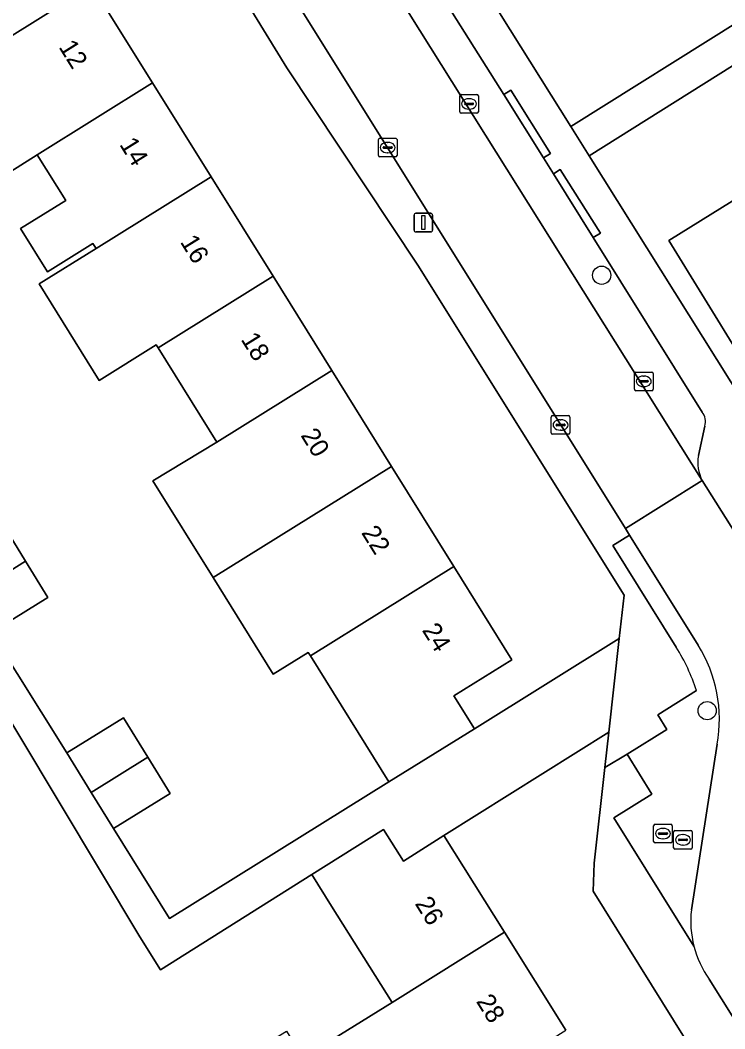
# Model space of a CAD drawing. Extents: x 159352 to 160617, y 385888 to 387323.
# Drawn here: x 159633.7 to 159671.4, y 386029 to 386083.1 of the extents above; entities that cross this region are included whole.
import ezdxf

# ---------------------------------------------------------------- set-up
doc = ezdxf.new("R2010")
doc.units = 0
for name, color, linetype in [('IMGEO_Boom', 7, 'Continuous'), ('IMGEO_Erf', 7, 'Continuous'), ('IMGEO_Kolk', 7, 'Continuous'), ('IMGEO_Lichtmast', 7, 'Continuous'), ('IMGEO_Pand', 7, 'Continuous'), ('IMGEO_Pand_nummerreeks', 7, 'Continuous'), ('IMGEO_Parkeervlak_open', 7, 'Continuous'), ('IMGEO_Rijbaan_lokaal_open', 7, 'Continuous'), ('IMGEO_Rioolput', 7, 'Continuous'), ('IMGEO_Voetpad_gesloten', 7, 'Continuous'), ('IMGEO_Voetpad_open', 7, 'Continuous')]:
    doc.layers.add(name, color=color, linetype=linetype)

msp = doc.modelspace()

# ---------------------------------------------------------------- linework, layer by layer
at = {"layer": 'IMGEO_Boom'}
for centre in [(159664.845, 386069.396), (159670.504, 386046.035)]:
    msp.add_circle(centre, 0.489, dxfattribs=at)
at = {"layer": 'IMGEO_Erf'}
for points in [[(159627.21, 386134.74), (159663.189, 386077.37), (159672.327, 386083.101)], [(159633.335, 386090.188), (159633.988, 386090.595), (159637.508, 386084.943), (159640.76, 386079.72), (159643.901, 386074.676), (159647.225, 386069.338), (159650.372, 386064.285), (159653.576, 386059.14), (159656.924, 386053.763), (159660.035, 386048.768), (159656.92, 386046.828), (159658.02, 386045.063), (159665.788, 386049.899), (159666.048, 386052.236), (159654.99, 386069.935), (159647.967, 386080.518), (159644.145, 386086.744), (159642.808, 386089.045), (159635.064, 386101.827), (159618.898, 386127.7)], [(159682.021, 386086.971), (159675.765, 386083.062), (159677.645, 386080.051), (159675.693, 386078.833), (159673.743, 386077.616), (159671.864, 386080.628), (159664.171, 386075.803), (159675.622, 386057.544), (159678.147, 386053.368), (159680.364, 386052.973), (159727.06, 386082.254), (159727.834, 386084.857)], [(159715.741, 386083.528), (159710.62, 386080.324), (159705.257, 386076.97), (159700.341, 386073.894), (159694.987, 386070.545), (159689.802, 386067.302), (159684.835, 386064.194), (159679.316, 386060.742), (159677.344, 386063.895), (159674.183, 386061.917), (159668.443, 386071.26), (159671.836, 386073.379), (159671.913, 386073.256), (159673.873, 386070.118), (159679.098, 386073.381), (159679.277, 386073.094), (159684.247, 386076.198), (159689.434, 386079.437), (159694.775, 386082.772), (159696.55, 386079.963), (159701.469, 386083.035), (159701.464, 386083.043), (159699.747, 386085.796)], [(159632.649, 386056.162), (159633.952, 386054.046), (159635.149, 386052.102), (159632.11, 386050.23), (159636.161, 386043.768), (159639.201, 386045.64), (159640.501, 386043.529), (159641.701, 386041.58), (159638.662, 386039.708), (159641.668, 386034.881), (159653.436, 386042.209), (159649.228, 386048.967), (159649.107, 386049.161), (159647.231, 386047.993), (159644.004, 386053.176), (159640.778, 386058.358), (159644.204, 386060.439), (159641.057, 386065.493), (159640.957, 386065.654), (159637.903, 386063.751), (159634.677, 386068.927), (159637.732, 386070.832), (159637.564, 386071.102), (159635.122, 386069.581), (159633.679, 386071.898), (159636.102, 386073.407), (159634.575, 386075.859), (159630.164, 386073.091)], [(159657.055, 386018.155), (159655.352, 386020.863), (159653.88, 386023.203), (159652.165, 386025.931), (159652.161, 386025.928), (159649.796, 386025.831), (159647.968, 386024.7), (159646.105, 386023.548), (159644.243, 386026.558), (159646.106, 386027.71), (159647.934, 386028.841), (159648.826, 386027.399), (159653.609, 386030.374), (159650.359, 386035.544), (159649.294, 386037.237), (159641.179, 386032.132), (159640.082, 386033.894), (159625.017, 386059.01)], [(159676.127, 386017.48), (159664.396, 386036.344), (159664.447, 386037.85), (159665.019, 386042.984), (159665.23, 386044.882), (159656.379, 386039.338), (159659.625, 386034.156), (159662.923, 386028.89)]]:
    msp.add_lwpolyline(points, dxfattribs=at)
at = {"layer": 'IMGEO_Kolk'}
for p, q in [((159657.231, 386078.164), (159657.231, 386079.016)), ((159657.306, 386079.09), (159658.158, 386079.09)), ((159657.49, 386078.584), (159657.49, 386078.596)), ((159657.533, 386078.633), (159657.931, 386078.633)), ((159657.719, 386078.87), (159657.744, 386078.87)), ((159657.974, 386078.596), (159657.974, 386078.584)), ((159658.232, 386079.016), (159658.232, 386078.164)), ((159658.158, 386078.09), (159657.306, 386078.09)), ((159657.928, 386078.547), (159657.53, 386078.547)), ((159657.742, 386078.31), (159657.717, 386078.31)), ((159652.871, 386075.819), (159652.871, 386076.671)), ((159652.946, 386076.745), (159653.798, 386076.745)), ((159653.359, 386076.525), (159653.384, 386076.525)), ((159653.872, 386076.671), (159653.872, 386075.819)), ((159653.13, 386076.239), (159653.13, 386076.251)), ((159653.568, 386076.202), (159653.17, 386076.202)), ((159653.173, 386076.288), (159653.571, 386076.288)), ((159653.382, 386075.965), (159653.357, 386075.965)), ((159653.614, 386076.251), (159653.614, 386076.239)), ((159653.798, 386075.745), (159652.946, 386075.745)), ((159666.602, 386063.276), (159666.602, 386064.128)), ((159666.677, 386064.202), (159667.529, 386064.202)), ((159667.09, 386063.982), (159667.115, 386063.982)), ((159667.603, 386064.128), (159667.603, 386063.276)), ((159666.861, 386063.696), (159666.861, 386063.708)), ((159667.299, 386063.659), (159666.901, 386063.659)), ((159666.904, 386063.745), (159667.302, 386063.745)), ((159667.113, 386063.422), (159667.088, 386063.422)), ((159667.345, 386063.708), (159667.345, 386063.696)), ((159667.529, 386063.202), (159666.677, 386063.202)), ((159662.138, 386060.936), (159662.138, 386061.788)), ((159662.213, 386061.862), (159663.065, 386061.862)), ((159663.139, 386061.788), (159663.139, 386060.936)), ((159662.397, 386061.356), (159662.397, 386061.368)), ((159662.835, 386061.319), (159662.437, 386061.319)), ((159662.44, 386061.405), (159662.838, 386061.405)), ((159662.626, 386061.642), (159662.651, 386061.642)), ((159662.881, 386061.368), (159662.881, 386061.356)), ((159663.065, 386060.862), (159662.213, 386060.862)), ((159662.649, 386061.082), (159662.624, 386061.082))]:
    msp.add_line(p, q, dxfattribs=at)
for points in [[(159657.231, 386078.164), (159657.231, 386079.016)], [(159657.306, 386079.09), (159658.158, 386079.09)], [(159658.232, 386079.016), (159658.232, 386078.164)], [(159658.158, 386078.09), (159657.306, 386078.09)], [(159652.871, 386075.819), (159652.871, 386076.671)], [(159652.946, 386076.745), (159653.798, 386076.745)], [(159653.872, 386076.671), (159653.872, 386075.819)], [(159653.798, 386075.745), (159652.946, 386075.745)], [(159666.602, 386063.276), (159666.602, 386064.128)], [(159666.677, 386064.202), (159667.529, 386064.202)], [(159667.603, 386064.128), (159667.603, 386063.276)], [(159667.529, 386063.202), (159666.677, 386063.202)], [(159662.138, 386060.936), (159662.138, 386061.788)], [(159662.213, 386061.862), (159663.065, 386061.862)], [(159663.139, 386061.788), (159663.139, 386060.936)], [(159663.065, 386060.862), (159662.213, 386060.862)]]:
    msp.add_lwpolyline(points, dxfattribs=at)
for centre, radius, start, end in [((159657.308, 386079.014), 0.0765, 91.552, 178.448), ((159657.308, 386079.014), 0.0765, 91.552, 178.448), ((159657.53, 386078.593), 0.0403, 85.8775, 175.7526), ((159657.527, 386078.583), 0.0366, 178.938, 274.7102), ((159657.931, 386078.59), 0.043, 264.8664, 352.4533), ((159657.935, 386078.595), 0.0386, 1.7309, 96.639), ((159658.156, 386079.014), 0.0765, 1.552, 88.448), ((159658.156, 386079.014), 0.0765, 1.552, 88.448), ((159657.308, 386078.166), 0.0765, 181.552, 268.448), ((159657.308, 386078.166), 0.0765, 181.552, 268.448), ((159658.156, 386078.166), 0.0765, 271.552, 358.448), ((159658.156, 386078.166), 0.0765, 271.552, 358.448), ((159652.948, 386076.669), 0.0765, 91.552, 178.448), ((159652.948, 386076.669), 0.0765, 91.552, 178.448), ((159653.796, 386076.669), 0.0765, 1.552, 88.448), ((159653.796, 386076.669), 0.0765, 1.552, 88.448), ((159653.17, 386076.248), 0.0403, 85.8775, 175.7526), ((159653.167, 386076.238), 0.0366, 178.938, 274.7102), ((159653.571, 386076.245), 0.043, 264.8664, 352.4533), ((159653.575, 386076.25), 0.0386, 1.7309, 96.639), ((159652.948, 386075.821), 0.0765, 181.552, 268.448), ((159652.948, 386075.821), 0.0765, 181.552, 268.448), ((159653.796, 386075.821), 0.0765, 271.552, 358.448), ((159653.796, 386075.821), 0.0765, 271.552, 358.448), ((159666.679, 386064.126), 0.0765, 91.552, 178.448), ((159666.679, 386064.126), 0.0765, 91.552, 178.448), ((159667.527, 386064.126), 0.0765, 1.552, 88.448), ((159667.527, 386064.126), 0.0765, 1.552, 88.448), ((159666.901, 386063.705), 0.0403, 85.8775, 175.7526), ((159666.898, 386063.695), 0.0366, 178.938, 274.7102), ((159667.302, 386063.702), 0.043, 264.8664, 352.4533), ((159667.306, 386063.707), 0.0386, 1.7309, 96.639), ((159666.679, 386063.278), 0.0765, 181.552, 268.448), ((159666.679, 386063.278), 0.0765, 181.552, 268.448), ((159667.527, 386063.278), 0.0765, 271.552, 358.448), ((159667.527, 386063.278), 0.0765, 271.552, 358.448), ((159662.215, 386061.786), 0.0765, 91.552, 178.448), ((159662.215, 386061.786), 0.0765, 91.552, 178.448), ((159663.063, 386061.786), 0.0765, 1.552, 88.448), ((159663.063, 386061.786), 0.0765, 1.552, 88.448), ((159662.437, 386061.365), 0.0403, 85.8775, 175.7526), ((159662.434, 386061.355), 0.0366, 178.938, 274.7102), ((159662.838, 386061.362), 0.043, 264.8664, 352.4533), ((159662.842, 386061.367), 0.0386, 1.7309, 96.639), ((159662.215, 386060.938), 0.0765, 181.552, 268.448), ((159662.215, 386060.938), 0.0765, 181.552, 268.448), ((159663.063, 386060.938), 0.0765, 271.552, 358.448), ((159663.063, 386060.938), 0.0765, 271.552, 358.448)]:
    msp.add_arc(centre, radius, start, end, dxfattribs=at)
for centre, major_axis, ratio, start_param, end_param in [((159657.718, 386078.59), (-0.387, 0.002), 0.722429, 4.712389, 7.853982), ((159657.743, 386078.59), (-0.39, 0.002), 0.717154, 1.570796, 4.712389), ((159653.358, 386076.245), (-0.387, 0.002), 0.722429, 4.712389, 7.853982), ((159653.383, 386076.245), (-0.39, 0.002), 0.717154, 1.570796, 4.712389), ((159667.089, 386063.702), (-0.387, 0.002), 0.722429, 4.712389, 7.853982), ((159667.114, 386063.702), (-0.39, 0.002), 0.717154, 1.570796, 4.712389), ((159662.625, 386061.362), (-0.387, 0.002), 0.722429, 4.712389, 7.853982), ((159662.65, 386061.362), (-0.39, 0.002), 0.717154, 1.570796, 4.712389)]:
    msp.add_ellipse(centre, major_axis=major_axis, ratio=ratio, start_param=start_param, end_param=end_param, dxfattribs=at)
at = {"layer": 'IMGEO_Lichtmast'}
for p, q in [((159654.784, 386071.818), (159654.784, 386072.618)), ((159654.784, 386072.618), (159654.784, 386071.818)), ((159654.884, 386072.718), (159655.674, 386072.718)), ((159655.674, 386072.718), (159654.884, 386072.718)), ((159655.774, 386072.618), (159655.774, 386071.818)), ((159655.774, 386071.818), (159655.774, 386072.618)), ((159655.674, 386071.718), (159654.884, 386071.718)), ((159654.884, 386071.718), (159655.674, 386071.718))]:
    msp.add_line(p, q, dxfattribs=at)
msp.add_lwpolyline([(159655.204, 386072.593), (159655.354, 386072.593), (159655.354, 386071.843), (159655.204, 386071.843), (159655.204, 386072.593)], dxfattribs=at)
for centre, start, end in [((159654.884, 386072.618), 90, 180), ((159654.884, 386072.618), 90, 180), ((159655.674, 386072.618), 0, 90), ((159655.674, 386072.618), 360, 90), ((159654.884, 386071.818), 180, 270), ((159654.884, 386071.818), 180, 270), ((159655.674, 386071.818), 270, 0), ((159655.674, 386071.818), 270, 0)]:
    msp.add_arc(centre, 0.1, start, end, dxfattribs=at)
at = {"layer": 'IMGEO_Pand'}
for points in [[(159628.789, 386079.509), (159637.508, 386084.943), (159633.988, 386090.595), (159633.335, 386090.188), (159631.369, 386093.346), (159627.125, 386090.704), (159623.305, 386088.325), (159625.42, 386084.93), (159627.206, 386082.05)], [(159640.76, 386079.72), (159637.508, 386084.943), (159628.789, 386079.509), (159626.901, 386078.332), (159624.337, 386076.711), (159627.574, 386071.502), (159630.164, 386073.091), (159634.575, 386075.859)], [(159634.575, 386075.859), (159636.102, 386073.407), (159633.679, 386071.898), (159635.122, 386069.581), (159637.564, 386071.102), (159637.732, 386070.832), (159643.901, 386074.676), (159640.76, 386079.72)], [(159643.901, 386074.676), (159637.732, 386070.832), (159634.677, 386068.927), (159637.903, 386063.751), (159640.957, 386065.654), (159641.057, 386065.493), (159647.225, 386069.338)], [(159679.098, 386073.381), (159673.873, 386070.118), (159671.913, 386073.256), (159671.836, 386073.379), (159668.443, 386071.26), (159674.183, 386061.917), (159677.344, 386063.895), (159679.316, 386060.742), (159684.835, 386064.194), (159679.277, 386073.094)], [(159641.057, 386065.493), (159644.204, 386060.439), (159650.372, 386064.285), (159647.225, 386069.338)], [(159644.204, 386060.439), (159640.778, 386058.358), (159644.004, 386053.176), (159653.576, 386059.14), (159650.372, 386064.285)], [(159644.004, 386053.176), (159647.231, 386047.993), (159649.107, 386049.161), (159649.228, 386048.967), (159656.924, 386053.763), (159653.576, 386059.14)], [(159632.649, 386056.162), (159629.609, 386054.29), (159630.923, 386052.158), (159633.952, 386054.046)], [(159632.11, 386050.23), (159635.149, 386052.102), (159633.952, 386054.046), (159630.923, 386052.158)], [(159649.228, 386048.967), (159653.436, 386042.209), (159658.02, 386045.063), (159656.92, 386046.828), (159660.035, 386048.768), (159656.924, 386053.763)], [(159639.201, 386045.64), (159636.161, 386043.768), (159637.472, 386041.641), (159640.501, 386043.529)], [(159638.662, 386039.708), (159641.701, 386041.58), (159640.501, 386043.529), (159637.472, 386041.641)], [(159653.609, 386030.374), (159659.625, 386034.156), (159656.379, 386039.338), (159654.21, 386037.964), (159653.146, 386039.658), (159649.294, 386037.237), (159650.359, 386035.544)], [(159662.923, 386028.89), (159659.625, 386034.156), (159653.609, 386030.374), (159648.826, 386027.399), (159649.796, 386025.831), (159652.161, 386025.928), (159652.165, 386025.931), (159653.88, 386023.203), (159656.916, 386025.112)]]:
    msp.add_lwpolyline(points, close=True, dxfattribs=at)
at = {"layer": 'IMGEO_Parkeervlak_open'}
for points in [[(159626.512, 386128.107), (159670.239, 386058.378)], [(159670.242, 386062.057), (159664.392, 386071.428), (159662.26, 386074.831), (159661.719, 386075.692), (159659.596, 386079.097), (159656.115, 386084.635), (159653.983, 386088.042), (159647.039, 386099.116), (159644.917, 386102.518), (159632.416, 386122.422), (159629.965, 386126.37)], [(159670.034, 386059.718), (159670.381, 386061.303)], [(159670.019, 386049.55), (159666.336, 386055.453), (159665.438, 386054.888), (159668.845, 386049.431)], [(159669.924, 386047.11), (159667.856, 386045.816), (159668.331, 386045.027), (159666.211, 386043.692), (159667.526, 386041.555), (159665.503, 386040.276), (159669.792, 386033.391)], [(159669.657, 386035.343), (159671.038, 386044.235)]]:
    msp.add_lwpolyline(points, dxfattribs=at)
for centre, radius, start, end in [((159669.491, 386061.529), 0.918, 345.7688, 35.1217), ((159672.021, 386059.336), 2.024, 169.1278, 208.2681), ((159660.275, 386044.036), 10.126, 17.6727, 32.1934), ((159663.605, 386045.565), 7.551, 349.8541, 31.8521), ((159674.943, 386034.728), 5.322, 173.3631, 194.5494)]:
    msp.add_arc(centre, radius, start, end, dxfattribs=at)
at = {"layer": 'IMGEO_Rijbaan_lokaal_open'}
msp.add_lwpolyline([(159641.564, 386095.152), (159645.806, 386088.37), (159647.92, 386084.96), (159666.118, 386055.802), (159670.239, 386058.378), (159626.512, 386128.107), (159625.752, 386129.326), (159621.761, 386126.823), (159624.572, 386122.299), (159628.257, 386116.428), (159635.697, 386104.535), (159638.89, 386099.412), (159639.428, 386098.549)], close=True, dxfattribs=at)
for points in [[(159674.287, 386051.938), (159670.239, 386058.378), (159666.118, 386055.802), (159666.336, 386055.453), (159670.019, 386049.55)], [(159671.038, 386044.235), (159669.657, 386035.343)], [(159670.612, 386031.633), (159672.6, 386028.467), (159676.243, 386030.847), (159675.949, 386031.202), (159674.928, 386032.924)]]:
    msp.add_lwpolyline(points, dxfattribs=at)
for centre, radius, start, end in [((159663.605, 386045.565), 7.551, 349.8541, 31.8521), ((159674.943, 386034.728), 5.322, 173.3631, 194.5494), ((159674.998, 386034.749), 5.381, 194.6212, 215.3912)]:
    msp.add_arc(centre, radius, start, end, dxfattribs=at)
at = {"layer": 'IMGEO_Rioolput'}
for p, q in [((159667.632, 386039.01), (159667.632, 386039.862)), ((159667.707, 386039.936), (159668.559, 386039.936)), ((159668.12, 386039.716), (159668.145, 386039.716)), ((159668.633, 386039.862), (159668.633, 386039.01)), ((159668.777, 386039.602), (159669.629, 386039.602)), ((159667.891, 386039.43), (159667.891, 386039.442)), ((159668.329, 386039.393), (159667.931, 386039.393)), ((159667.934, 386039.479), (159668.332, 386039.479)), ((159668.143, 386039.156), (159668.118, 386039.156)), ((159668.375, 386039.442), (159668.375, 386039.43)), ((159668.702, 386038.676), (159668.702, 386039.528)), ((159668.961, 386039.096), (159668.961, 386039.108)), ((159669.399, 386039.059), (159669.001, 386039.059)), ((159669.004, 386039.145), (159669.402, 386039.145)), ((159669.19, 386039.382), (159669.215, 386039.382)), ((159669.445, 386039.108), (159669.445, 386039.096)), ((159669.703, 386039.528), (159669.703, 386038.676)), ((159668.559, 386038.936), (159667.707, 386038.936)), ((159669.629, 386038.602), (159668.777, 386038.602)), ((159669.213, 386038.822), (159669.188, 386038.822))]:
    msp.add_line(p, q, dxfattribs=at)
for points in [[(159667.632, 386039.01), (159667.632, 386039.862)], [(159667.707, 386039.936), (159668.559, 386039.936)], [(159668.633, 386039.862), (159668.633, 386039.01)], [(159668.777, 386039.602), (159669.629, 386039.602)], [(159668.702, 386038.676), (159668.702, 386039.528)], [(159669.703, 386039.528), (159669.703, 386038.676)], [(159668.559, 386038.936), (159667.707, 386038.936)], [(159669.629, 386038.602), (159668.777, 386038.602)]]:
    msp.add_lwpolyline(points, dxfattribs=at)
for centre, radius, start, end in [((159667.709, 386039.86), 0.0765, 91.552, 178.448), ((159667.709, 386039.86), 0.0765, 91.552, 178.448), ((159668.557, 386039.86), 0.0765, 1.552, 88.448), ((159668.557, 386039.86), 0.0765, 1.552, 88.448), ((159668.779, 386039.526), 0.0765, 91.552, 178.448), ((159668.779, 386039.526), 0.0765, 91.552, 178.448), ((159669.627, 386039.526), 0.0765, 1.552, 88.448), ((159669.627, 386039.526), 0.0765, 1.552, 88.448), ((159667.931, 386039.439), 0.0403, 85.8775, 175.7526), ((159667.928, 386039.429), 0.0366, 178.938, 274.7102), ((159668.332, 386039.436), 0.043, 264.8664, 352.4533), ((159668.336, 386039.441), 0.0386, 1.7309, 96.639), ((159669.001, 386039.105), 0.0403, 85.8775, 175.7526), ((159668.998, 386039.095), 0.0366, 178.938, 274.7102), ((159669.402, 386039.102), 0.043, 264.8664, 352.4533), ((159669.406, 386039.107), 0.0386, 1.7309, 96.639), ((159667.709, 386039.012), 0.0765, 181.552, 268.448), ((159667.709, 386039.012), 0.0765, 181.552, 268.448), ((159668.557, 386039.012), 0.0765, 271.552, 358.448), ((159668.557, 386039.012), 0.0765, 271.552, 358.448), ((159668.779, 386038.678), 0.0765, 181.552, 268.448), ((159668.779, 386038.678), 0.0765, 181.552, 268.448), ((159669.627, 386038.678), 0.0765, 271.552, 358.448), ((159669.627, 386038.678), 0.0765, 271.552, 358.448)]:
    msp.add_arc(centre, radius, start, end, dxfattribs=at)
for centre, major_axis, ratio, start_param, end_param in [((159668.119, 386039.436), (-0.387, 0.002), 0.722429, 4.712389, 7.853982), ((159668.144, 386039.436), (-0.39, 0.002), 0.717154, 1.570796, 4.712389), ((159669.189, 386039.102), (-0.387, 0.002), 0.722429, 4.712389, 7.853982), ((159669.214, 386039.102), (-0.39, 0.002), 0.717154, 1.570796, 4.712389)]:
    msp.add_ellipse(centre, major_axis=major_axis, ratio=ratio, start_param=start_param, end_param=end_param, dxfattribs=at)
at = {"layer": 'IMGEO_Voetpad_gesloten'}
msp.add_lwpolyline([(159672.327, 386083.101), (159663.189, 386077.37), (159664.171, 386075.803), (159671.864, 386080.628), (159673.813, 386081.844), (159675.765, 386083.062), (159682.021, 386086.971)], dxfattribs=at)
at = {"layer": 'IMGEO_Voetpad_open'}
for points in [[(159675.699, 386050.365), (159680.364, 386052.973), (159678.147, 386053.368), (159675.622, 386057.544), (159664.171, 386075.803), (159663.189, 386077.37), (159627.21, 386134.74)], [(159668.845, 386049.431), (159665.438, 386054.888), (159666.336, 386055.453), (159666.118, 386055.802), (159647.92, 386084.96), (159647.546, 386084.725), (159645.418, 386088.134), (159645.806, 386088.37), (159641.564, 386095.152), (159641.176, 386094.91), (159639.046, 386098.327), (159639.428, 386098.549), (159638.89, 386099.412), (159638.511, 386099.168), (159635.326, 386104.296), (159635.697, 386104.535), (159628.257, 386116.428), (159627.886, 386116.189), (159624.211, 386122.054), (159624.572, 386122.299), (159621.761, 386126.823), (159620.473, 386128.883)], [(159618.898, 386127.7), (159635.064, 386101.827), (159642.808, 386089.045), (159644.145, 386086.744), (159647.967, 386080.518), (159654.99, 386069.935), (159666.048, 386052.236), (159665.788, 386049.899), (159665.23, 386044.882), (159665.019, 386042.984), (159666.211, 386043.692), (159668.331, 386045.027), (159667.856, 386045.816), (159669.924, 386047.11)], [(159629.965, 386126.37), (159632.416, 386122.422), (159644.917, 386102.518), (159645.294, 386102.758), (159647.424, 386099.344), (159647.039, 386099.116), (159653.983, 386088.042), (159654.359, 386088.279), (159656.498, 386084.869), (159656.115, 386084.635), (159659.596, 386079.097), (159659.965, 386079.334), (159662.104, 386075.928), (159661.719, 386075.692), (159662.26, 386074.831), (159662.612, 386075.077), (159664.773, 386071.662), (159664.392, 386071.428), (159670.242, 386062.057)], [(159670.381, 386061.303), (159670.034, 386059.718)], [(159625.017, 386059.01), (159640.082, 386033.894), (159641.179, 386032.132), (159649.294, 386037.237), (159653.146, 386039.658), (159654.21, 386037.964), (159656.379, 386039.338), (159665.23, 386044.882), (159665.788, 386049.899), (159658.02, 386045.063), (159653.436, 386042.209), (159641.668, 386034.881), (159638.662, 386039.708), (159637.472, 386041.641), (159636.161, 386043.768), (159632.11, 386050.23)], [(159670.239, 386058.378), (159674.287, 386051.938)], [(159669.792, 386033.391), (159665.503, 386040.276), (159667.526, 386041.555), (159666.211, 386043.692), (159665.019, 386042.984), (159664.447, 386037.85), (159664.396, 386036.344), (159676.127, 386017.48), (159684.463, 386004.075), (159683.777, 386003.638), (159726.677, 385934.766), (159729.867, 385936.632), (159729.606, 385937.026), (159729.51, 385937.17)], [(159689.128, 386002.021), (159688.743, 386001.782), (159686.576, 386005.278), (159686.951, 386005.519), (159685.883, 386007.217), (159685.522, 386006.976), (159675.629, 386022.83), (159676.012, 386023.063), (159672.6, 386028.467), (159670.612, 386031.633)]]:
    msp.add_lwpolyline(points, dxfattribs=at)
for points in [[(159659.596, 386079.097), (159661.719, 386075.692), (159662.104, 386075.928), (159659.965, 386079.334)], [(159664.392, 386071.428), (159664.773, 386071.662), (159662.612, 386075.077), (159662.26, 386074.831)]]:
    msp.add_lwpolyline(points, close=True, dxfattribs=at)
for centre, radius, start, end in [((159669.491, 386061.529), 0.918, 345.7688, 35.1217), ((159672.021, 386059.336), 2.024, 169.1278, 208.2681), ((159660.275, 386044.036), 10.126, 17.6727, 32.1934), ((159674.998, 386034.749), 5.381, 194.6212, 215.3912)]:
    msp.add_arc(centre, radius, start, end, dxfattribs=at)

# ---------------------------------------------------------------- texts
at = {"layer": 'IMGEO_Pand_nummerreeks'}
for s, rotation, p in [('12', 301.9135, (159635.697, 386081.644)), ('14', 301.9118, (159638.954, 386076.415)), ('16', 301.9135, (159642.21, 386071.186)), ('18', 301.9118, (159645.468, 386065.955)), ('20', 301.9118, (159648.676, 386060.804)), ('22', 301.9118, (159651.928, 386055.582)), ('24', 301.9118, (159655.185, 386050.35)), ('26', 302.0594, (159654.802, 386035.677)), ('28', 302.0568, (159658.084, 386030.436))]:
    msp.add_text(s, height=1, rotation=rotation, dxfattribs=at).set_placement(p)

doc.saveas('drawing.dxf')
